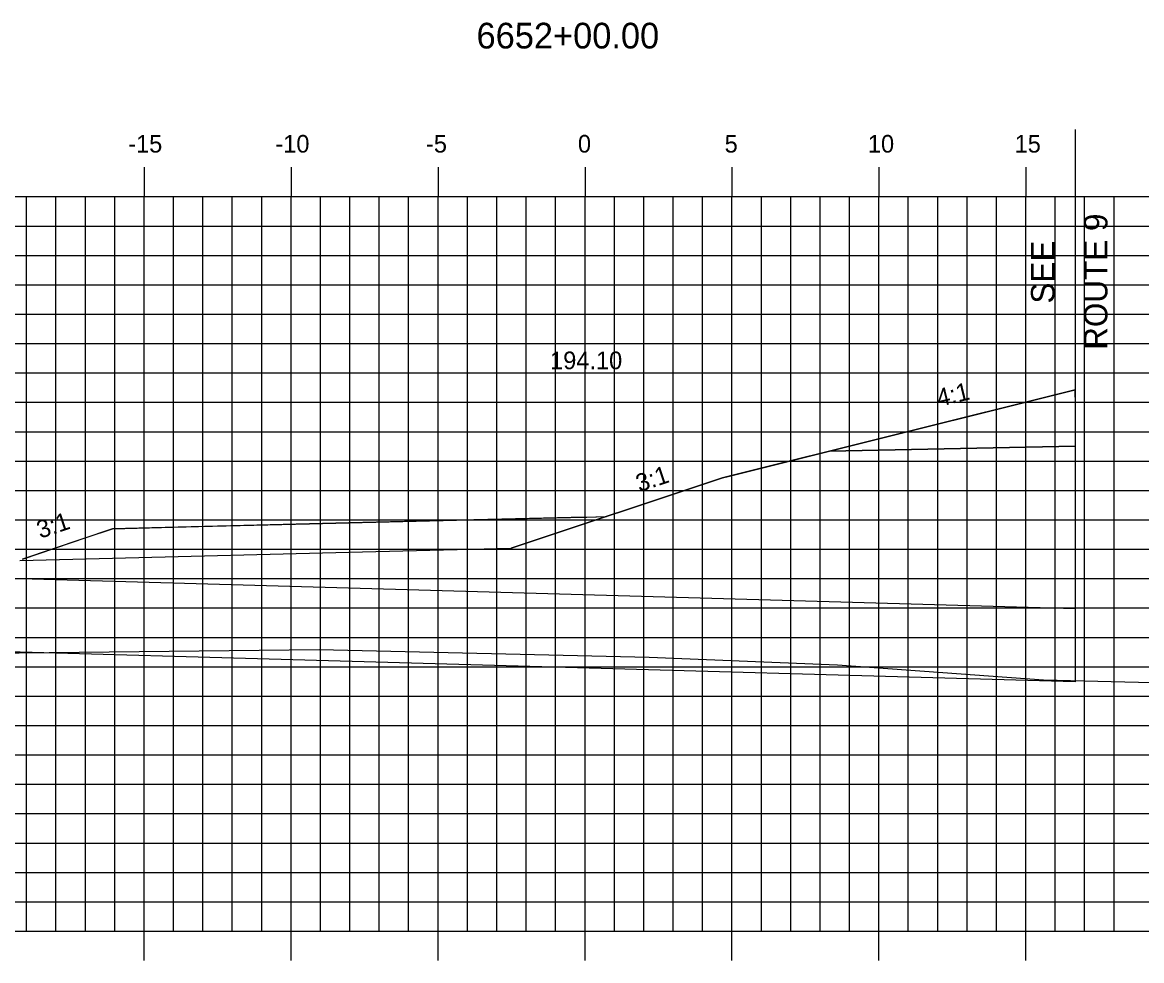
# Model space of a CAD drawing. Extents: x 1723764 to 1723936, y 458501 to 458611.
# Drawn here: x 1723828.4 to 1723866.48, y 458544.25 to 458576.19 of the extents above; entities that cross this region are included whole.
import ezdxf

# ---------------------------------------------------------------- set-up
doc = ezdxf.new("R2010")
doc.units = 0
for name, color, linetype in [('ANNOTATION', 7, 'Continuous'), ('D_Drainage_Culvert', 7, 'Continuous'), ('D_Roadway_Centerline', 7, 'Continuous'), ('D_Roadway_Centerline_Text', 7, 'Continuous'), ('D_Roadway_Drive_Gravel', 7, 'Continuous'), ('D_Roadway_Edge_Shoulder', 7, 'Continuous'), ('D_Roadway_SlopeLines', 7, 'Continuous'), ('D_Roadway_SubGrade', 7, 'Continuous'), ('H_V ANNOTATION', 7, 'Continuous'), ('MAJOR', 7, 'Continuous'), ('MINOR', 7, 'Continuous'), ('S_Roadway_Centerline', 7, 'Continuous')]:
    doc.layers.add(name, color=color, linetype=linetype)

msp = doc.modelspace()

# ---------------------------------------------------------------- linework, layer by layer
msp.add_lwpolyline([(1723828.399, 458557.919), (1723830.601, 458558.66), (1723831.467, 458558.952), (1723834.394, 458559.024), (1723838.171, 458559.118), (1723839.505, 458559.151), (1723844.093, 458559.264), (1723847.542, 458559.35), (1723847.606, 458559.351), (1723848.275, 458559.368)])
at = {"layer": 'D_Drainage_Culvert'}
msp.add_lwpolyline([(1723864.22, 458553.738), (1723822.272, 458554.924), (1723822.339, 458557.423), (1723864.22, 458556.239)], dxfattribs=at)
at = {"layer": 'D_Roadway_Centerline'}
msp.add_lwpolyline([(1723845.035, 458558.288), (1723852.22, 458560.682), (1723852.453, 458560.741), (1723855.857, 458561.592), (1723856.394, 458561.726), (1723864.22, 458563.682)], dxfattribs=at)
at = {"layer": 'D_Roadway_Drive_Gravel'}
for points in [[(1723847.542, 458559.35), (1723839.504, 458559.151), (1723831.467, 458558.952), (1723828.399, 458557.919)], [(1723828.309, 458557.874), (1723831.467, 458557.952), (1723839.504, 458558.151), (1723845.035, 458558.288)]]:
    msp.add_lwpolyline(points, dxfattribs=at)
at = {"layer": 'D_Roadway_Edge_Shoulder'}
msp.add_line((1723864.22, 458563.682), (1723864.22, 458563.432), dxfattribs=at)
msp.add_line((1723864.22, 458563.682), (1723864.22, 458563.432), dxfattribs=at)
at = {"layer": 'D_Roadway_SlopeLines'}
for points in [[(1723864.22, 458563.682), (1723852.22, 458560.682), (1723845.035, 458558.288)], [(1723864.22, 458563.682), (1723852.22, 458560.682), (1723845.035, 458558.288)], [(1723864.22, 458563.682), (1723852.22, 458560.682), (1723845.035, 458558.288)], [(1723864.22, 458563.682), (1723852.22, 458560.682), (1723845.035, 458558.288)], [(1723864.22, 458563.682), (1723852.22, 458560.682), (1723845.035, 458558.288)], [(1723864.22, 458563.682), (1723852.22, 458560.682), (1723845.035, 458558.288)], [(1723864.22, 458563.682), (1723852.22, 458560.682)], [(1723864.22, 458563.682), (1723852.22, 458560.682)], [(1723864.22, 458563.682), (1723855.857, 458561.592)], [(1723847.542, 458559.35), (1723848.275, 458559.368)], [(1723831.467, 458558.952), (1723828.399, 458557.919)]]:
    msp.add_lwpolyline(points, dxfattribs=at)
at = {"layer": 'D_Roadway_SubGrade'}
for p, q in [((1723864.22, 458572.541), (1723864.22, 458561.759)), ((1723864.22, 458561.759), (1723864.22, 458553.738))]:
    msp.add_line(p, q, dxfattribs=at)
for points in [[(1723864.22, 458561.759), (1723855.857, 458561.592), (1723864.22, 458563.682), (1723864.22, 458563.432)], [(1723864.22, 458563.432), (1723864.22, 458563.682), (1723855.857, 458561.592), (1723864.22, 458561.759)], [(1723864.22, 458561.759), (1723855.857, 458561.592), (1723864.22, 458563.682), (1723864.22, 458563.432)], [(1723864.22, 458561.759), (1723855.857, 458561.592), (1723864.22, 458563.682), (1723864.22, 458563.432)]]:
    msp.add_lwpolyline(points, dxfattribs=at)
at = {"layer": 'MAJOR'}
for p, q in [((1723832.542, 458571.256), (1723832.542, 458570.254)), ((1723837.542, 458571.256), (1723837.542, 458570.254)), ((1723842.542, 458571.256), (1723842.542, 458570.254)), ((1723847.542, 458571.256), (1723847.542, 458570.254)), ((1723852.542, 458571.256), (1723852.542, 458570.254)), ((1723857.542, 458571.256), (1723857.542, 458570.254)), ((1723862.542, 458571.256), (1723862.542, 458570.254)), ((1723777.542, 458570.254), (1723917.542, 458570.254)), ((1723777.542, 458570.254), (1723917.542, 458570.254)), ((1723832.542, 458545.254), (1723832.542, 458570.254)), ((1723837.542, 458545.254), (1723837.542, 458570.254)), ((1723842.542, 458545.254), (1723842.542, 458570.254)), ((1723847.542, 458545.254), (1723847.542, 458570.254)), ((1723852.542, 458545.254), (1723852.542, 458570.254)), ((1723857.542, 458545.254), (1723857.542, 458570.254)), ((1723862.542, 458545.254), (1723862.542, 458570.254)), ((1723777.542, 458565.254), (1723917.542, 458565.254)), ((1723777.542, 458560.254), (1723917.542, 458560.254)), ((1723777.542, 458555.254), (1723917.542, 458555.254)), ((1723777.542, 458550.254), (1723917.542, 458550.254)), ((1723777.542, 458545.254), (1723917.542, 458545.254)), ((1723777.542, 458545.254), (1723917.542, 458545.254)), ((1723832.542, 458544.252), (1723832.542, 458545.254)), ((1723837.542, 458544.252), (1723837.542, 458545.254)), ((1723842.542, 458544.252), (1723842.542, 458545.254)), ((1723847.542, 458544.252), (1723847.542, 458545.254)), ((1723852.542, 458544.252), (1723852.542, 458545.254)), ((1723857.542, 458544.252), (1723857.542, 458545.254)), ((1723862.542, 458544.252), (1723862.542, 458545.254))]:
    msp.add_line(p, q, dxfattribs=at)
at = {"layer": 'MINOR'}
for p, q in [((1723828.542, 458545.254), (1723828.542, 458570.254)), ((1723829.542, 458545.254), (1723829.542, 458570.254)), ((1723830.542, 458545.254), (1723830.542, 458570.254)), ((1723831.542, 458545.254), (1723831.542, 458570.254)), ((1723833.542, 458545.254), (1723833.542, 458570.254)), ((1723834.542, 458545.254), (1723834.542, 458570.254)), ((1723835.542, 458545.254), (1723835.542, 458570.254)), ((1723836.542, 458545.254), (1723836.542, 458570.254)), ((1723838.542, 458545.254), (1723838.542, 458570.254)), ((1723839.542, 458545.254), (1723839.542, 458570.254)), ((1723840.542, 458545.254), (1723840.542, 458570.254)), ((1723841.542, 458545.254), (1723841.542, 458570.254)), ((1723843.542, 458545.254), (1723843.542, 458570.254)), ((1723844.542, 458545.254), (1723844.542, 458570.254)), ((1723845.542, 458545.254), (1723845.542, 458570.254)), ((1723846.542, 458545.254), (1723846.542, 458570.254)), ((1723848.542, 458545.254), (1723848.542, 458570.254)), ((1723849.542, 458545.254), (1723849.542, 458570.254)), ((1723850.542, 458545.254), (1723850.542, 458570.254)), ((1723851.542, 458545.254), (1723851.542, 458570.254)), ((1723853.542, 458545.254), (1723853.542, 458570.254)), ((1723854.542, 458545.254), (1723854.542, 458570.254)), ((1723855.542, 458545.254), (1723855.542, 458570.254)), ((1723856.542, 458545.254), (1723856.542, 458570.254)), ((1723858.542, 458545.254), (1723858.542, 458570.254)), ((1723859.542, 458545.254), (1723859.542, 458570.254)), ((1723860.542, 458545.254), (1723860.542, 458570.254)), ((1723861.542, 458545.254), (1723861.542, 458570.254)), ((1723863.542, 458545.254), (1723863.542, 458570.254)), ((1723864.542, 458545.254), (1723864.542, 458570.254)), ((1723865.542, 458545.254), (1723865.542, 458570.254)), ((1723777.542, 458569.254), (1723917.542, 458569.254)), ((1723777.542, 458568.254), (1723917.542, 458568.254)), ((1723777.542, 458567.254), (1723917.542, 458567.254)), ((1723777.542, 458566.254), (1723917.542, 458566.254)), ((1723777.542, 458564.254), (1723917.542, 458564.254)), ((1723777.542, 458563.254), (1723917.542, 458563.254)), ((1723777.542, 458562.254), (1723917.542, 458562.254)), ((1723777.542, 458561.254), (1723917.542, 458561.254)), ((1723777.542, 458559.254), (1723917.542, 458559.254)), ((1723777.542, 458558.254), (1723917.542, 458558.254)), ((1723777.542, 458557.254), (1723917.542, 458557.254)), ((1723777.542, 458556.254), (1723917.542, 458556.254)), ((1723777.542, 458554.254), (1723917.542, 458554.254)), ((1723777.542, 458553.254), (1723917.542, 458553.254)), ((1723777.542, 458552.254), (1723917.542, 458552.254)), ((1723777.542, 458551.254), (1723917.542, 458551.254)), ((1723777.542, 458549.254), (1723917.542, 458549.254)), ((1723777.542, 458548.254), (1723917.542, 458548.254)), ((1723777.542, 458547.254), (1723917.542, 458547.254)), ((1723777.542, 458546.254), (1723917.542, 458546.254))]:
    msp.add_line(p, q, dxfattribs=at)
at = {"layer": 'S_Roadway_Centerline'}
msp.add_lwpolyline([(1723777.542, 458555.901), (1723777.899, 458555.886), (1723781.729, 458555.712), (1723784.914, 458555.809), (1723792.946, 458556.04), (1723804.299, 458555.71), (1723805.143, 458555.656), (1723805.732, 458555.623), (1723817.844, 458555.138), (1723827.379, 458554.731), (1723828.288, 458554.733), (1723838.5, 458554.836), (1723849.73, 458554.584), (1723856.129, 458554.317), (1723863.147, 458553.81), (1723870.978, 458553.613), (1723876.204, 458553.497), (1723881.901, 458553.314), (1723891.771, 458553.149), (1723909.916, 458552.356), (1723912.425, 458552.215), (1723917.542, 458552.075)], dxfattribs=at)

# ---------------------------------------------------------------- texts
at = {"layer": 'ANNOTATION'}
for s, height, rotation, p in [('ROUTE 9', 0.8, 90, (1723865.317, 458565.041)), ('SEE', 0.8, 90, (1723863.517, 458566.616)), ('4:1', 0.6, 13.6162, (1723859.588, 458563.098)), ('3:1', 0.6, 18.4349, (1723849.392, 458560.194)), ('3:1', 0.6, 18.4349, (1723829.007, 458558.61))]:
    msp.add_text(s, height=height, rotation=rotation, dxfattribs=at).set_placement(p)
at = {"layer": 'D_Roadway_Centerline_Text'}
msp.add_text('194.10', height=0.6, dxfattribs=at).set_placement((1723846.354, 458564.382))
at = {"layer": 'H_V ANNOTATION'}
for s, height, p in [('6652+00.00', 0.875, (1723843.851, 458575.297)), ('-15', 0.6, (1723831.999, 458571.754)), ('-10', 0.6, (1723837.007, 458571.754)), ('-5', 0.6, (1723842.132, 458571.754)), ('0', 0.6, (1723847.301, 458571.754)), ('5', 0.6, (1723852.293, 458571.754)), ('10', 0.6, (1723857.167, 458571.754)), ('15', 0.6, (1723862.159, 458571.754))]:
    msp.add_text(s, height=height, dxfattribs=at).set_placement(p)

doc.saveas('drawing.dxf')
